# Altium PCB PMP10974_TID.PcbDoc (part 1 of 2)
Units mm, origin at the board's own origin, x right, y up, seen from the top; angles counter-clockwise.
Board outline 80 x 60 mm, 2 copper layers (Top Layer, Bottom Layer), stack 1.575 mm thick; 90 components, 52 nets, 298 pads, 61 vias.
Unrouted connection lines stored in the file: 1.
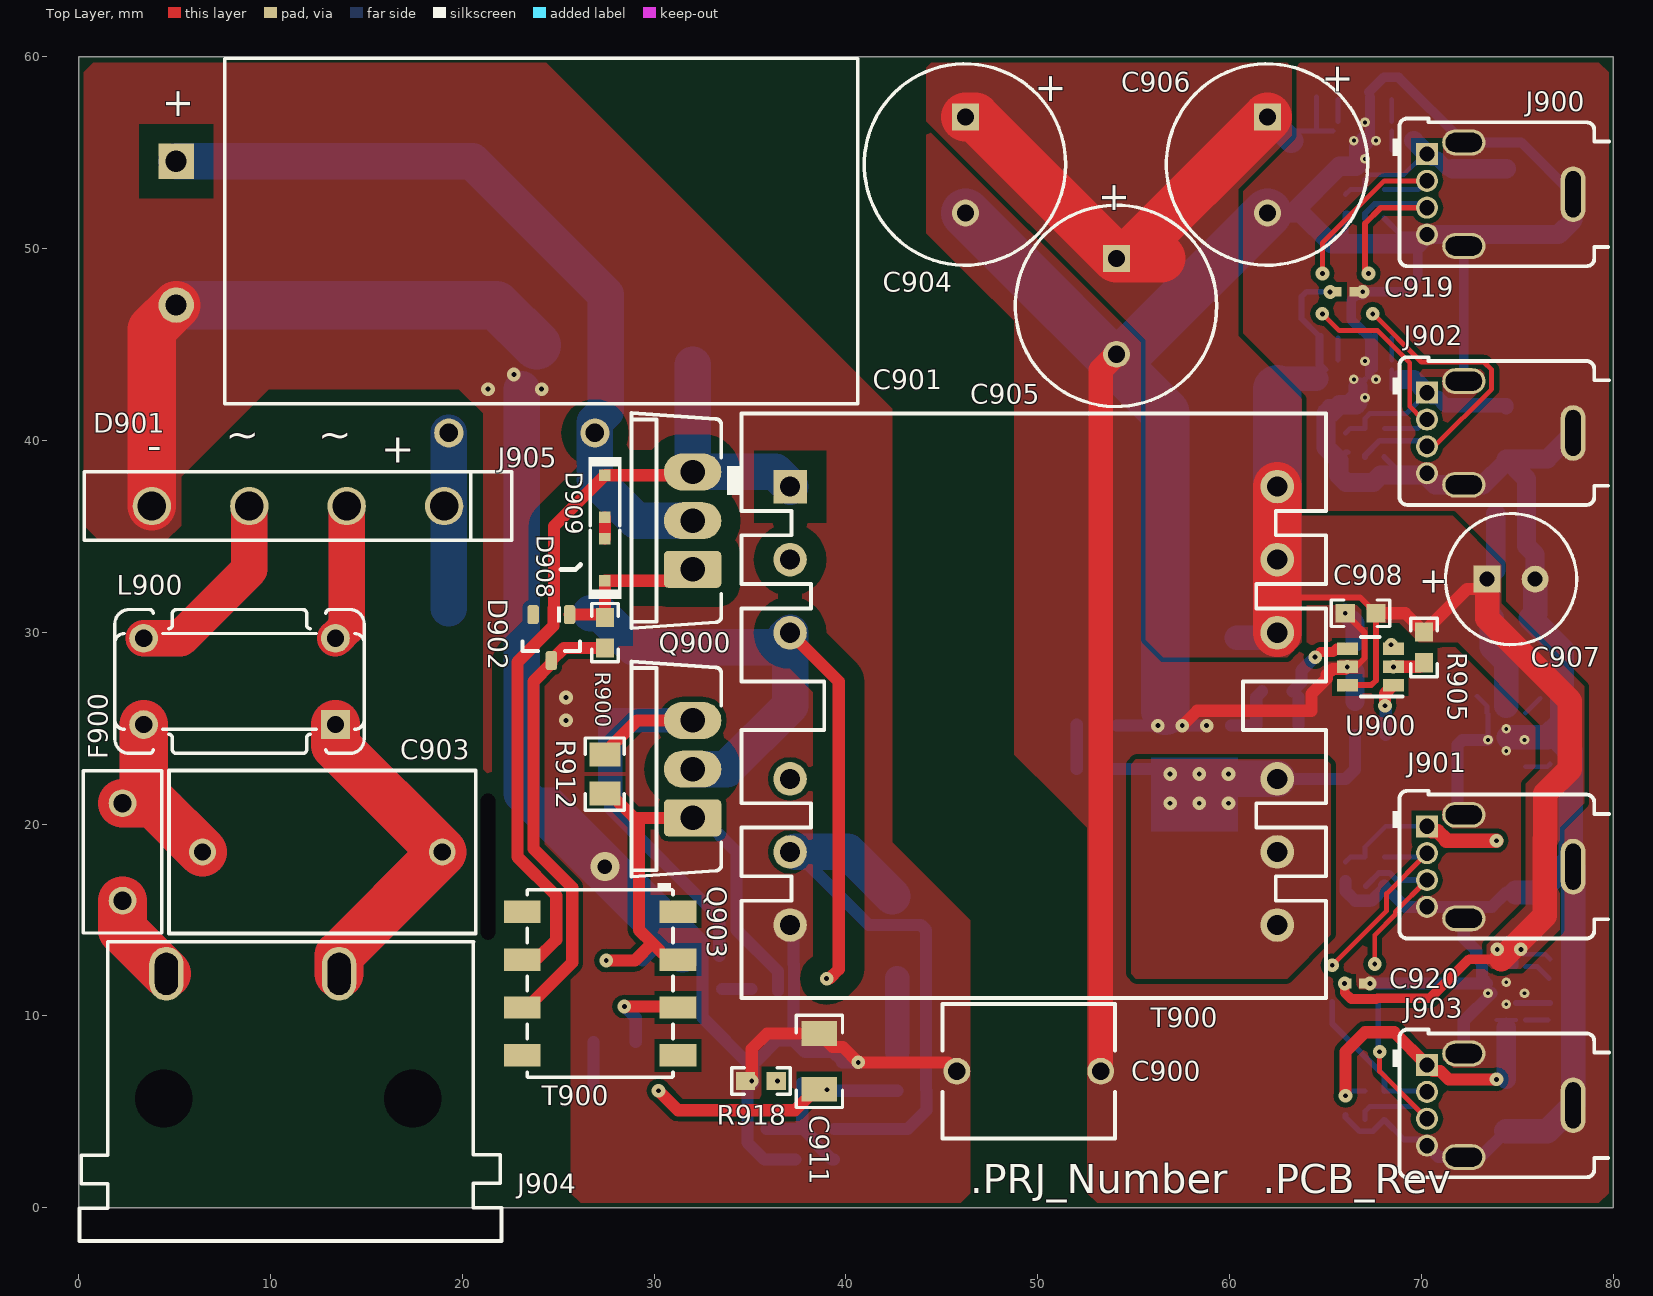
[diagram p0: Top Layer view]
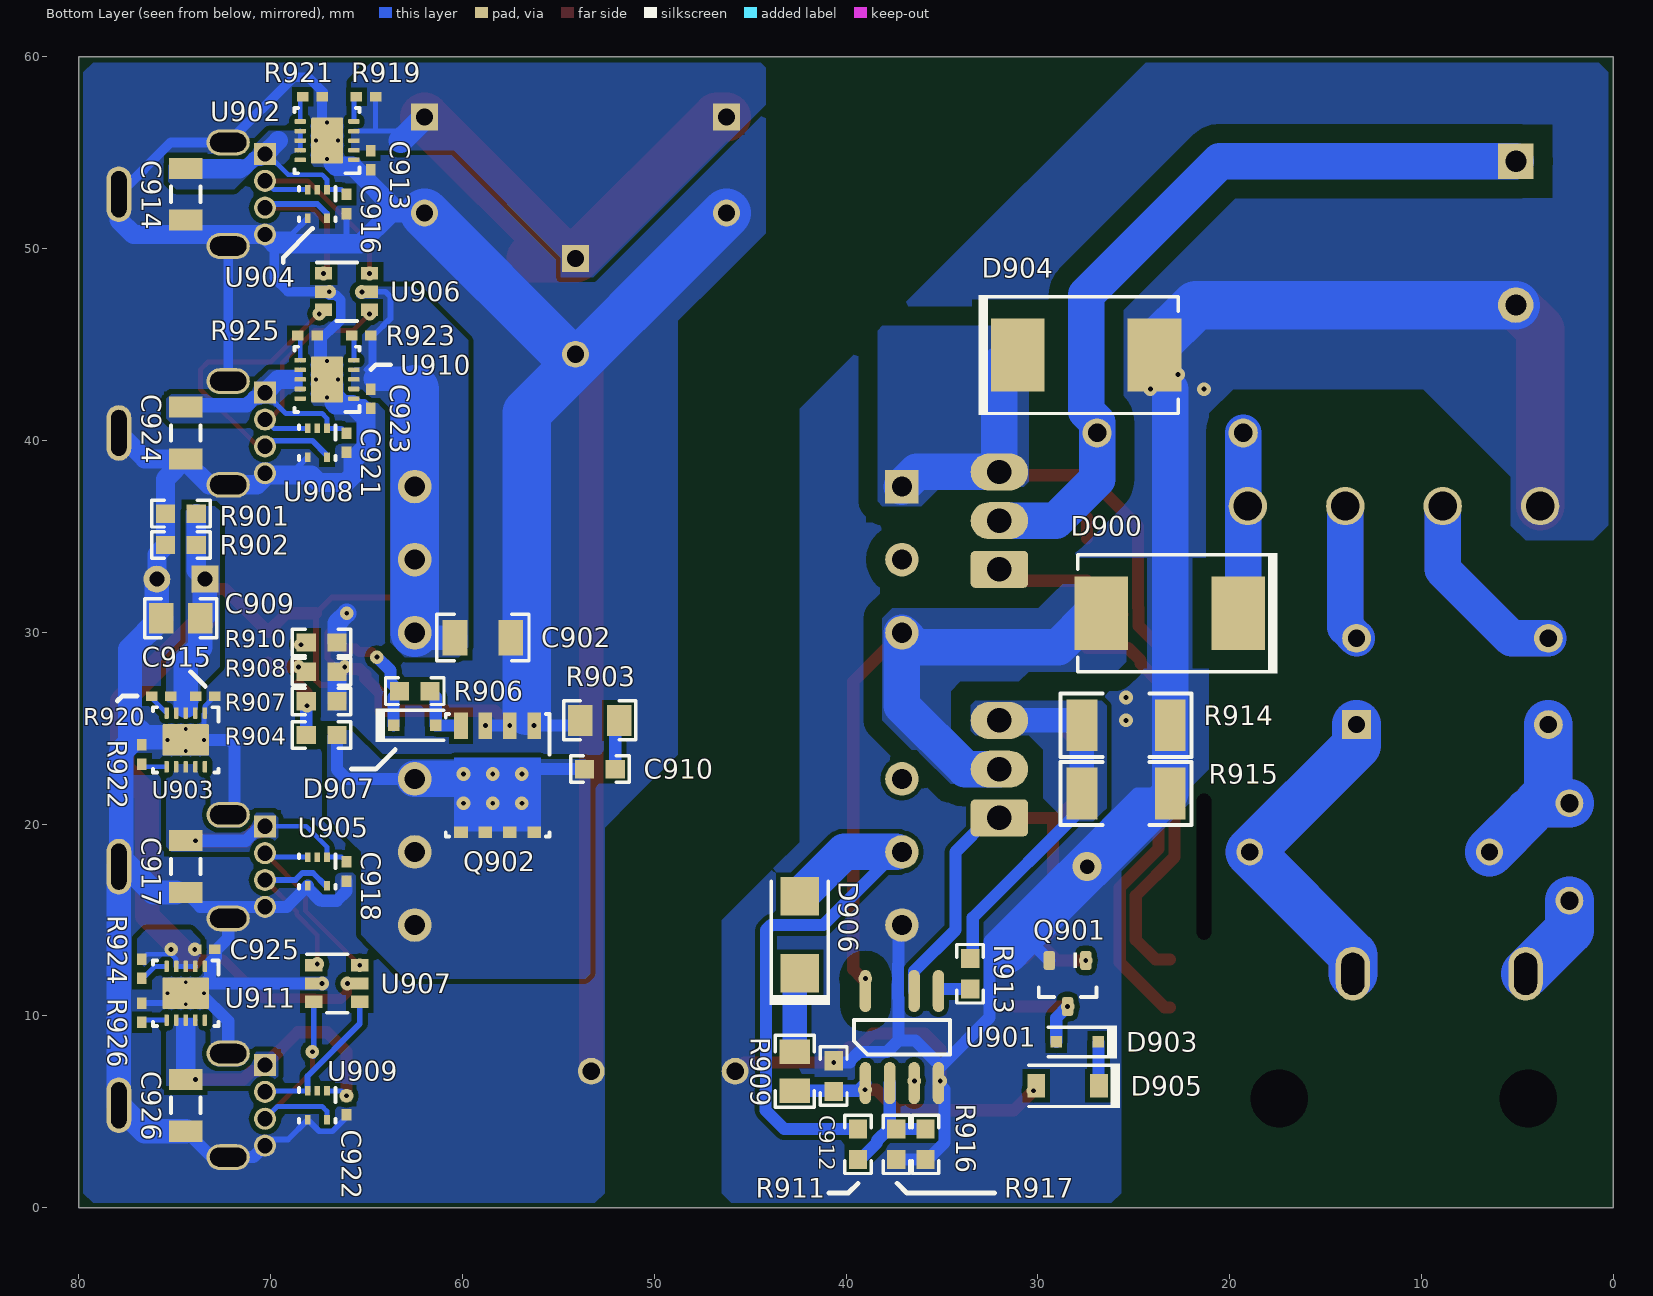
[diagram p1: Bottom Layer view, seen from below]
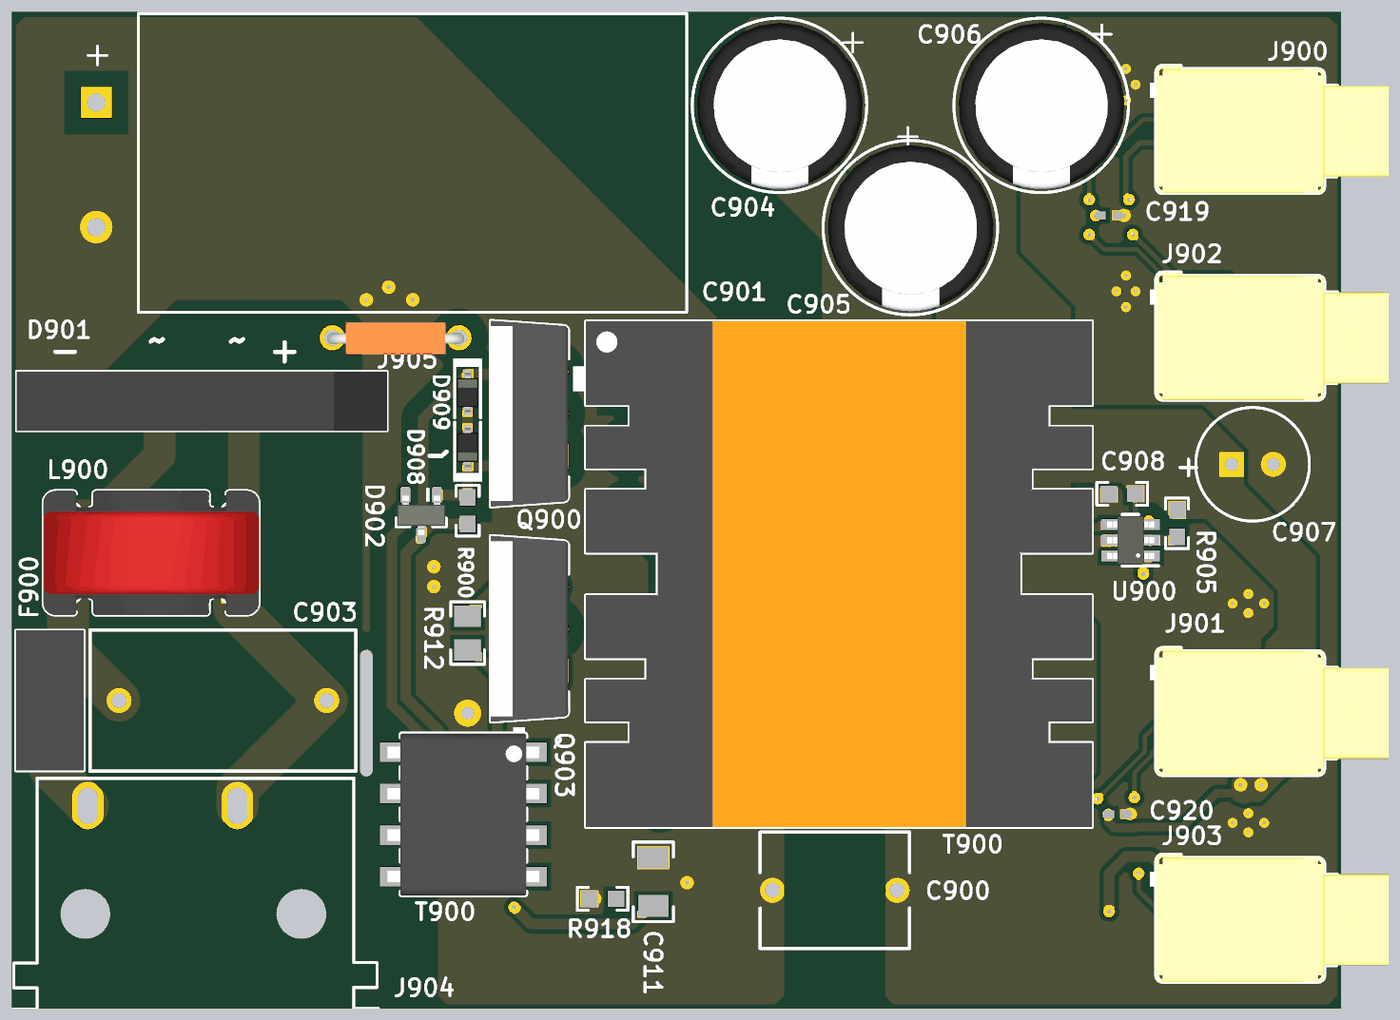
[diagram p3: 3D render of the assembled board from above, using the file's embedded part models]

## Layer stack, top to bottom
Top Solder: solder mask 0.0102, Solder Resist, Dk 3.5
Top Layer: signal copper 0.0356
Dielectric1: core 1.5037, FR-4, Dk 4.8
Bottom Layer: signal copper 0.0356
Bottom Solder: solder mask 0.0102, Solder Resist, Dk 3.5

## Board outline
0,0 80,0 80,60 0,60

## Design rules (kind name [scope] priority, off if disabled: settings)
AcuteAngle [All] p1: minimum=4.50000000000000E+0001 checktracksonly=FALSE
AssemblyTestPointUsage [All] p1: valid=2
Clearance Clearance_1 [InNetClass('HV') vs InNet('GND')] p1: gap=1
Clearance Clearance_Keepouts [((IsTrack Or IsArc) And Not InPoly) And IsFree and IsKeepOut vs ((IsTrack Or IsArc) And Not InPoly) And IsFree and IsKeepOut] p2: gap=0
Clearance Clearance_BoardEdge_MountingHoles [OnCopper and InComponentClass('Mounting Holes') vs IsKeepOut] p3: gap=1.016
Clearance Clearance_BoardEdge_Poly [OnCopper and InPoly vs IsKeepOut] p4: gap=0.635
Clearance Clearance_BoardEdge [OnCopper and Not InComponentClass('Logo') and not InComponentClass('FiducialMark') and not InRegion(1000,500,4000,800) and Not IsKeepout vs IsKeepOut] p5: gap=1.905
Clearance Clearance_Poly [InPolygon] p6: gap=0.254
Clearance [All] p7: gap=0.2
ComponentClearance ComponentClearance_MountingHoles_FiducialMarks [InComponentClass('Mounting Holes') vs InComponentClass('FiducialMark')] p1: gap=0.508 collisioncheckmode=3 verticalgap=0.254 showdistances=FALSE
ComponentClearance ComponentClearance_Shunt [InComponentClass('Header') vs InComponentClass('Shunt')] p2: gap=0 collisioncheckmode=3 verticalgap=0 showdistances=FALSE
ComponentClearance ComponentClearance_Logo [InComponentClass('Logo')] p3: gap=0.127 collisioncheckmode=3 verticalgap=0.254 showdistances=FALSE
ComponentClearance ComponentClearance_ScrewToNut [(HasFootprint('NY PMS 440 0025 PH')) vs (HasFootprint('Keystone_1902C'))] p4: gap=0.508 collisioncheckmode=3 verticalgap=2540 showdistances=FALSE
ComponentClearance ComponentClearance_MountingHoles [InComponentClass('Mounting Holes')] p5: gap=0.508 collisioncheckmode=3 verticalgap=0.254 showdistances=FALSE
ComponentClearance ComponentClearance_SmallPassives [HasFootprint('0201*') or HasFootprint('0402*') or HasFootprint('0508') or HasFootprint('0603*') or HasFootprint('0612') or HasFootprint('0805*') or HasFootprint('0815*') or HasFootprint('0830*') or HasFootprint('1206*') or HasFootprint('1210*') or HasFootprint('1808*') or HasFootprint('1812*') or HasFootprint('1825*') or HasFootprint('2010*') or HasFootprint('2220*') or HasFootprint('2225*') or HasFootprint('2512*') or HasFootprint('2728*') or HasFootprint('3518*') vs HasFootprint('0201*') or HasFootprint('0402*') or HasFootprint('0508') or HasFootprint('0603*') or HasFootprint('0612') or HasFootprint('0805*') or HasFootprint('0815*') or HasFootprint('0830*') or HasFootprint('1206*') or HasFootprint('1210*') or HasFootprint('1808*') or HasFootprint('1812*') or HasFootprint('1825*') or HasFootprint('2010*') or HasFootprint('2220*') or HasFootprint('2225*') or HasFootprint('2512*') or HasFootprint('2728*') or HasFootprint('3518*')] p6: gap=0.508 collisioncheckmode=3 verticalgap=0.508 showdistances=FALSE
ComponentClearance ComponentClearance_THtoSMT [IsThruComponent vs IsSMTComponent] p7: gap=0.254 collisioncheckmode=3 verticalgap=0.254 showdistances=FALSE
ComponentClearance ComponentClearance_THtoTH [IsThruComponent vs IsThruComponent] p8: gap=0.254 collisioncheckmode=3 verticalgap=0.254 showdistances=FALSE
ComponentClearance [All] p9: gap=0.254 collisioncheckmode=3 verticalgap=0.254 showdistances=FALSE
DiffPairsRouting [All] p1: maxlimit=2.54 minlimit=0.254 mostfreqgap=0.254 toplayer_minwidth=0.381 toplayer_maxwidth=0.381 toplayer_prefwidth=0.381 bottomlayer_minwidth=0.381 bottomlayer_maxwidth=0.381 bottomlayer_prefwidth=0.381 maxuncoupledlength=25.4
FabricationTestPointUsage TestPointUsage [All] p1: valid=2 allowmultiple=FALSE
FabricationTestpoint Testpoint [All] p1: side=3 testpointundercomponent=TRUE minsize=1.016 maxsize=2.54 preferedsize=1.524 minholesize=0 maxholesize=1.016 preferedholesize=0.813 testpointgrid=0.025 allowsidetop=TRUE allowsidebottom=TRUE usegrid=TRUE gridtolerance=0
FanoutControl Fanout_LCC [IsLCC] p1: bgadir=Out bgaviamode=Centered fanoutstyle=Auto fanoutdirection=Alternating viagrid=0.025 // Fanout_LCC (Default Rule)
FanoutControl Fanout_BGA [IsBGA] p2: bgadir=Out bgaviamode=Centered fanoutstyle=Auto fanoutdirection=Alternating viagrid=0.025 // Fanout_BGA (Default Rule)
FanoutControl Fanout_Default [All] p4: bgadir=Out bgaviamode=Centered fanoutstyle=Auto fanoutdirection=Alternating viagrid=0.025 // Fanout_Default (Default Rule)
FanoutControl Fanout_Small [(CompPinCount < 5)] p5: bgadir=Out bgaviamode=Centered fanoutstyle=Auto fanoutdirection=OutThenIn viagrid=0.025 // Fanout_Small (Default Rule)
Height [All] p1: minheight=0 maxheight=76.2 prefheight=12.7
HoleSize [All] p1: absolutevalues=TRUE maxlimit=20 minlimit=0.178 maxpercent=80.000 minpercent=20.000
MinimumAnnularRing MinimumAnnularRing_ThermalPadVias [IsVia and InAnyComponent] p1: minimumring=0.15
MinimumAnnularRing [All] p2: minimumring=0.15
MinimumSolderMaskSliver MinimumSolderMaskSliver_Logo [InComponentClass('Logo') vs InComponentClass('Logo')] p1: minsoldermaskwidth=0.018
MinimumSolderMaskSliver [All] p2: minsoldermaskwidth=0.051
PlaneConnect [All] p1: planeconnectstyle=Relief reliefexpansion=0.254 reliefentries=4 reliefconductorwidth=0.254 reliefairgap=0.254
PolygonConnect PolygonConnect_12 [All vs IsNamedPolygon('C910_2') Or  IsNamedPolygon('C917_1') Or  IsNamedPolygon('GND') Or  IsNamedPolygon('Vout') Or  IsNamedPolygon('D904_1') Or  IsNamedPolygon('Vout') Or  IsNamedPolygon('C922_1') Or  IsNamedPolygon('C910_2') Or  IsNamedPolygon('Vout') Or  IsNamedPolygon('GND') Or  IsNamedPolygon('C914') Or  IsNamedPolygon('GND') Or  IsNamedPolygon('Vout') Or  IsNamedPolygon('Vout') Or  IsNamedPolygon('Q903_3') Or  IsNamedPolygon('C921_1') Or  IsNamedPolygon('D900_2') Or  IsNamedPolygon('Vout')] p1: connectstyle=Direct reliefconductorwidth=0.254 reliefentries=4 polygonreliefangle="90 Angle" airgapwidth=0.254
PolygonConnect PolygonConnect_11 [All vs IsNamedPolygon('Vout') Or  IsNamedPolygon('Vout') Or  IsNamedPolygon('Vout') Or  IsNamedPolygon('C917_1') Or  IsNamedPolygon('D904_1') Or  IsNamedPolygon('Vout') Or  IsNamedPolygon('D900_2') Or  IsNamedPolygon('C910_2') Or  IsNamedPolygon('Vout') Or  IsNamedPolygon('C921_1') Or  IsNamedPolygon('Q903_3') Or  IsNamedPolygon('Vout') Or  IsNamedPolygon('C914') Or  IsNamedPolygon('C922_1') Or  IsNamedPolygon('C910_2')] p2: connectstyle=Direct reliefconductorwidth=0.254 reliefentries=4 polygonreliefangle="90 Angle" airgapwidth=0.254
PolygonConnect PolygonConnect_10 [All vs IsNamedPolygon('Vout')] p3: connectstyle=Direct reliefconductorwidth=0.254 reliefentries=4 polygonreliefangle="90 Angle" airgapwidth=0.254
PolygonConnect PolygonConnect_9 [All vs IsNamedPolygon('C921_1') Or  IsNamedPolygon('D904_1') Or  IsNamedPolygon('Vout') Or  IsNamedPolygon('C914') Or  IsNamedPolygon('C917_1') Or  IsNamedPolygon('C910_2') Or  IsNamedPolygon('Vout') Or  IsNamedPolygon('Q903_3') Or  IsNamedPolygon('Vout') Or  IsNamedPolygon('Vout') Or  IsNamedPolygon('D900_2') Or  IsNamedPolygon('C910_2')] p4: connectstyle=Direct reliefconductorwidth=0.254 reliefentries=4 polygonreliefangle="90 Angle" airgapwidth=0.254
PolygonConnect PolygonConnect_8 [All vs IsNamedPolygon('C910_2') Or  IsNamedPolygon('D904_1') Or  IsNamedPolygon('Vout') Or  IsNamedPolygon('C910_2') Or  IsNamedPolygon('Q903_3') Or  IsNamedPolygon('C914') Or  IsNamedPolygon('D900_2') Or  IsNamedPolygon('Vout')] p5: connectstyle=Direct reliefconductorwidth=0.254 reliefentries=4 polygonreliefangle="90 Angle" airgapwidth=0.254
PolygonConnect PolygonConnect_7 [All vs IsNamedPolygon('C910_2') Or  IsNamedPolygon('Q903_3') Or  IsNamedPolygon('Vout') Or  IsNamedPolygon('Vout') Or  IsNamedPolygon('D904_1') Or  IsNamedPolygon('D900_2') Or  IsNamedPolygon('C910_2')] p6: connectstyle=Direct reliefconductorwidth=0.254 reliefentries=4 polygonreliefangle="90 Angle" airgapwidth=0.254
PolygonConnect PolygonConnect_6 [All vs IsNamedPolygon('GND2') Or  IsNamedPolygon('SGND') Or  IsNamedPolygon('GND1') Or  IsNamedPolygon('C901_1') Or  IsNamedPolygon('SGND') Or  IsNamedPolygon('GND2') Or  IsNamedPolygon('GND1')] p7: connectstyle=Direct reliefconductorwidth=0.254 reliefentries=4 polygonreliefangle="90 Angle" airgapwidth=0.254
PolygonConnect PolygonConnect_5 [All vs IsNamedPolygon('GND1') Or  IsNamedPolygon('GND1')] p8: connectstyle=Direct reliefconductorwidth=0.254 reliefentries=4 polygonreliefangle="90 Angle" airgapwidth=0.254
PolygonConnect PolygonConnect_4 [All vs IsNamedPolygon('C21_1') Or  IsNamedPolygon('C5_1') Or  IsNamedPolygon('C12_2') Or  IsNamedPolygon('C2_2') Or  IsNamedPolygon('C13_1') Or  IsNamedPolygon('C28_1') Or  IsNamedPolygon('C6_1') Or  IsNamedPolygon('GND') Or  IsNamedPolygon('GND2') Or  IsNamedPolygon('C14_1') Or  IsNamedPolygon('C13_1') Or  IsNamedPolygon('Q1_3') Or  IsNamedPolygon('C14_1') Or  IsNamedPolygon('C5_1') Or  IsNamedPolygon('GND2') Or  IsNamedPolygon('C28_1') Or  IsNamedPolygon('D5_2') Or  IsNamedPolygon('D6_2') Or  IsNamedPolygon('D2_1') Or  IsNamedPolygon('C12_2') Or  IsNamedPolygon('D2_1') Or  IsNamedPolygon('C4_1') Or  IsNamedPolygon('C4_1') Or  IsNamedPolygon('C2_2') Or  IsNamedPolygon('GND') Or  IsNamedPolygon('C33_1') Or  IsNamedPolygon('C9_1')] p9: connectstyle=Direct reliefconductorwidth=0.254 reliefentries=4 polygonreliefangle="90 Angle" airgapwidth=0.254
PolygonConnect PolygonConnect_3 [All vs IsNamedPolygon('C28_1') Or  IsNamedPolygon('C12_2') Or  IsNamedPolygon('C28_1') Or  IsNamedPolygon('C9_1') Or  IsNamedPolygon('D5_2') Or  IsNamedPolygon('C12_2') Or  IsNamedPolygon('C2_2') Or  IsNamedPolygon('C14_1') Or  IsNamedPolygon('C4_1') Or  IsNamedPolygon('C14_1') Or  IsNamedPolygon('D6_2') Or  IsNamedPolygon('GND2') Or  IsNamedPolygon('Q1_3') Or  IsNamedPolygon('C5_1') Or  IsNamedPolygon('D2_1') Or  IsNamedPolygon('C4_1') Or  IsNamedPolygon('C13_1') Or  IsNamedPolygon('C5_1') Or  IsNamedPolygon('C13_1') Or  IsNamedPolygon('C33_1') Or  IsNamedPolygon('D2_1') Or  IsNamedPolygon('GND') Or  IsNamedPolygon('GND') Or  IsNamedPolygon('GND2') Or  IsNamedPolygon('C2_2') Or  IsNamedPolygon('C6_1') Or  IsNamedPolygon('C21_1')] p10: connectstyle=Direct reliefconductorwidth=0.254 reliefentries=4 polygonreliefangle="90 Angle" airgapwidth=0.254
PolygonConnect PolygonConnect_2 [All vs IsNamedPolygon('C21_1') Or  IsNamedPolygon('C4_1') Or  IsNamedPolygon('D5_2') Or  IsNamedPolygon('C5_1') Or  IsNamedPolygon('C14_1') Or  IsNamedPolygon('C13_1') Or  IsNamedPolygon('C4_1') Or  IsNamedPolygon('C33_1') Or  IsNamedPolygon('C12_2') Or  IsNamedPolygon('D2_1') Or  IsNamedPolygon('C2_2') Or  IsNamedPolygon('C28_1') Or  IsNamedPolygon('C12_2') Or  IsNamedPolygon('D2_1') Or  IsNamedPolygon('C5_1') Or  IsNamedPolygon('Q1_3') Or  IsNamedPolygon('GND') Or  IsNamedPolygon('D6_2') Or  IsNamedPolygon('C6_1') Or  IsNamedPolygon('C2_2') Or  IsNamedPolygon('C14_1') Or  IsNamedPolygon('C28_1') Or  IsNamedPolygon('C13_1') Or  IsNamedPolygon('C9_1') Or  IsNamedPolygon('GND')] p11: connectstyle=Direct reliefconductorwidth=0.254 reliefentries=4 polygonreliefangle="90 Angle" airgapwidth=0.254
PolygonConnect PolygonConnect_1 [All vs IsNamedPolygon('C28_1') Or  IsNamedPolygon('D5_2') Or  IsNamedPolygon('C5_1') Or  IsNamedPolygon('C5_1') Or  IsNamedPolygon('D2_1') Or  IsNamedPolygon('C21_1') Or  IsNamedPolygon('C9_1') Or  IsNamedPolygon('C4_1') Or  IsNamedPolygon('C14_1') Or  IsNamedPolygon('C28_1') Or  IsNamedPolygon('C6_1') Or  IsNamedPolygon('C12_2') Or  IsNamedPolygon('C33_1') Or  IsNamedPolygon('C4_1') Or  IsNamedPolygon('C13_1') Or  IsNamedPolygon('C12_2') Or  IsNamedPolygon('D6_2') Or  IsNamedPolygon('C2_2') Or  IsNamedPolygon('C14_1') Or  IsNamedPolygon('D2_1') Or  IsNamedPolygon('C2_2') Or  IsNamedPolygon('C13_1')] p12: connectstyle=Direct reliefconductorwidth=0.254 reliefentries=4 polygonreliefangle="90 Angle" airgapwidth=0.254
PolygonConnect [All] p13: connectstyle=Relief reliefconductorwidth=0.254 reliefentries=4 polygonreliefangle="90 Angle" airgapwidth=0.254
RoutingVias ThermalPadVias [IsVia and InAnyComponent] p1: holewidth=0.2 width=0.5 viastyle="Through Hole" minholewidth=0.2 minwidth=0.5 maxholewidth=0.33 maxwidth=0.6
RoutingVias [All] p2: holewidth=0.406 width=0.864 viastyle="Through Hole" minholewidth=0.2 minwidth=0.66 maxholewidth=1.016 maxwidth=1.651
SilkToBoardRegionClearance [Not ((IsComment or IsDesignator) And (Hide <> 'False')) and not InRegion(1000,500,4000,800)] p1:
SilkToSilkClearance SilkToSilkClearance_Pb-FreeLogo [(HasFootprint('Pb-Free_Overlay_Medium') OR HasFootprint('Pb-Free_Overlay_Small')) vs (HasFootprint('Pb-Free_Overlay_Medium') OR HasFootprint('Pb-Free_Overlay_Small'))] p1: silktosilkclearance=0
SilkToSilkClearance [All] p2: silktosilkclearance=0.025
SilkToSolderMaskClearance "Silk to Solder Mask Opening" [All] p1: minsilkscreentomaskgap=0.025 clearancetoexposedcopper=FALSE
SolderMaskExpansion [All] p1: expansion=0.05
UnpouredPolygon [All] p1: allowunpoured=FALSE
Width [All] p1: maxlimit=2.54 minlimit=0.152 preferedwidth=0.254 checkconnectedcopper=TRUE
13 further rules are at their usual default settings.

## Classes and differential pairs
component class PMP10974_BlankSheet: !PCB900 C900 C901 C902 C903 C904 C905 C906 C907 C908 C909 C910 C911 C912 D900 D901 D902 D903 D904 D905 D906 D907 D908 D909 F900 J904 J905 L900 Q900 Q901 Q902 Q903 R900 R901 R902 R903 R904 R905 R906 R907 R908 R909 R910 R911 R912 R913 R914 R915 R916 R917 R918 T900 U900 U901
component class PMP10974_TID_Hardware: C913 C914 C915 C916 C917 C918 C919 C920 C921 C922 C923 C924 C925 C926 J900 J901 J902 J903 R919 R920 R921 R922 R923 R924 R925 R926 U902 U903 U904 U905 U906 U907 U908 U909 U910 U911
net class HV: NetC901_1 NetC903_1 NetC903_2 NetD900_1 NetD900_2 NetD901_2 NetD901_3 NetD902_1 NetD904_1

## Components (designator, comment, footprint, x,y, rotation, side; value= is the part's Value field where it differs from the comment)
C900 "DE6E3KJ222MN3A" E_900x700x900 49.53,7.112 r180 top
C901 "UPT2G101MHD6" CAPPR7.5-18X25 5.08,50.8 r270 top
C902 "1206YD226MAT2A" 1206 58.928,29.718 r180 bottom
C903 "890324024003" ECQUG_1500x800x1500 12.7,18.542 r0 top
C904 "PLE0J681MDO1" CAPPRD500W60D1000H1250 46.228,54.356 r270 top
C905 "PLE0J681MDO1" CAPPRD500W60D1000H1250 54.102,46.99 r270 top
C906 "PLE0J681MDO1" CAPPRD500W60D1000H1250 61.976,54.356 r270 top
C907 "6.3YXJ470M6.3X11" SEPC_C55 74.676,32.766 r0 top
C908 "C0603C105K4PACTU" 0603 66.828,30.988 r180 top
C909 "08053C104KAT2A" 0805_HV 74.676,30.734 r0 bottom
C910 "C1608C0G2A101J" 0603 52.832,22.86 r0 bottom
C911 "GRM316R61E225KA12D" 1206 38.608,7.62 r90 top
C912 "06035C104KAT2A" 0603 40.64,6.858 r90 bottom
C913 "GRM155R61A105KE15D" 0402L 64.77,54.61 r270 bottom
C914 "GRM31CR61A476KE15L" 1206L 74.422,52.832 r270 bottom
C915 "GRM155R61A105KE15D" 0402L 73.406,26.67 r180 bottom
C916 "C1005X5R0J104K" 0402L 66.04,52.324 r270 bottom
C917 "GRM31CR61A476KE15L" 1206L 74.422,17.78 r270 bottom
C918 "C1005X5R0J104K" 0402L 66.04,17.526 r270 bottom
C919 "GRM155R61A105KE15D" 0402L 66.04,47.752 r0 top
C920 "GRM155R61A105KE15D" 0402L 66.548,11.684 r0 top
C921 "C1005X5R0J104K" 0402L 66.04,39.878 r270 bottom
C922 "C1005X5R0J104K" 0402L 66.04,5.334 r270 bottom
C923 "GRM155R61A105KE15D" 0402L 64.77,42.164 r270 bottom
C924 "GRM31CR61A476KE15L" 1206L 74.422,40.386 r270 bottom
C925 "GRM155R61A105KE15D" 0402L 73.406,13.462 r180 bottom
C926 "GRM31CR61A476KE15L" 1206L 74.422,5.334 r270 bottom
D900 "MURS360T3G" SMC 23.114,30.988 r0 bottom
D901 "GBU4K-E3/45" GBU 11.43,36.576 r180 top
D902 "BAT54-7-F" SOT-23 24.638,29.718 r270 top
D903 "BAS316,115" sod-323 27.94,8.636 r0 bottom
D904 "MURS360T3G" SMC 27.483,44.45 r180 bottom
D905 "MMSZ5231B-7-F" SOD-123 28.448,6.35 r0 bottom
D906 "ES1D-13-F" SMA 42.418,14.224 r90 bottom
D907 "BAT54HT1G" sod-323 62.484,25.146 r180 bottom
D908 "BAT54HT1G" sod-323 27.432,33.782 r90 top
D909 "MMSZ5246BS-7-F" sod-323 27.432,37.084 r270 top
F900 "RST 500" Fuse_RST 2.286,18.542 r270 top
J900 "0894858000" Molex_0894858000 80,52.832 r0 top
J901 "0894858000" Molex_0894858000 80,17.78 r0 top
J902 "0894858000" Molex_0894858000 80,40.386 r0 top
J903 "0894858000" Molex_0894858000 80,5.334 r0 top
J904 "770W-X2/10" CONN_AC_770W-SERIES 10.922,8.89 r180 top
J905 "923345-03-C" 923345-03-C 23.1,40.386 r0 top
L900 "744821240" WE-CMB_XS 8.382,27.432 r180 top
Q900 "IPP50R380CE" TO-220AB 32.004,35.814 r90 top
Q901 "2N7002-7-F" SOT-23 28.448,11.684 r270 bottom
Q902 "CSD18502Q5B" TRANS_NexFET_Q5B 58.166,22.352 r270 bottom
Q903 "IPP50R380CE" TO-220AB 32.004,22.86 r90 top
R900 "CRCW06033R00JNEA" 0603 27.432,29.972 r90 top
R901 "CRCW0603100KJNEA" 0603 74.676,36.176 r180 bottom
R902 "CRCW06031K00JNEA" 0603 74.676,34.544 r180 bottom
R903 "CRCW08050000Z0EA" 0805_HV 52.832,25.4 r0 bottom
R904 "CRCW0603324KFKEA" 0603 67.336,24.638 r180 bottom
R905 "CRCW0603182KFKEA" 0603 70.13,29.21 r90 top
R906 "CRCW06030000Z0EA" 0603 62.484,26.924 r0 bottom
R907 "CRCW060310K0FKEA" 0603 67.336,26.394 r0 bottom
R908 "CRCW060330K1FKEA" 0603 67.336,27.94 r0 bottom
R909 "CRCW080510R0FKEA" 0805_HV 42.672,7.112 r90 bottom
R910 "CRCW060325K5FKEA" 0603 67.336,29.464 r180 bottom
R911 "CRCW0603133KFKEA" 0603 39.37,3.302 r90 bottom
R912 "CRCW0805100KJNEA" 0805_HV 27.432,22.606 r270 top
R913 "CRCW0603976RFKEA" 0603 33.528,12.192 r90 bottom
R914 "MCR50JZHFLR330" 2010 25.4,25.146 r0 bottom
R915 "CSRN2010FKR400" 2010 25.4,21.59 r0 bottom
R916 "CRCW060356K2FKEA" 0603 35.851,3.302 r90 bottom
R917 "CRCW060356K2FKEA" 0603 37.375,3.302 r90 bottom
R918 "CRCW060336K5FKEA" 0603 35.56,6.604 r0 top
R919 "CRCW040210K0FKED" 0402L 65.024,57.912 r180 bottom
R920 "CRCW040210K0FKED" 0402L 75.692,26.67 r180 bottom
R921 "CRCW040244K2FKED" 0402L 67.818,57.912 r0 bottom
R922 "CRCW040244K2FKED" 0402L 76.708,23.622 r270 bottom
R923 "CRCW040210K0FKED" 0402L 65.278,45.466 r180 bottom
R924 "CRCW040210K0FKED" 0402L 76.708,12.446 r90 bottom
R925 "CRCW040244K2FKED" 0402L 68.072,45.466 r0 bottom
R926 "CRCW040244K2FKED" 0402L 76.708,10.16 r270 bottom
T900 "760301302" Wurth_760301302 27.178,11.684 r270 top
T900 "RLTI-1132" Renco_RLTI-1132 49.784,26.162 r0 top
U900 "UCC24630DBV" DBV0006A_N 67.336,28.194 r180 top
U901 "UCC28730D" D0007A_N 37.084,8.89 r90 bottom
U902 "TPS2559DRC" DRC0010A 67.056,55.626 r0 bottom
U903 "TPS2559DRC" DRC0010A 74.422,24.384 r270 bottom
U904 "TPD2E001DRLR" DRL0005A 67.564,52.324 r270 bottom
U905 "TPD2E001DRLR" DRL0005A 67.564,17.526 r270 bottom
U906 "TPS2513DBV" DBV0006A_L 66.04,47.752 r180 bottom
U907 "TPS2513DBV" DBV0006A_L 66.548,11.684 r180 bottom
U908 "TPD2E001DRLR" DRL0005A 67.564,39.878 r270 bottom
U909 "TPD2E001DRLR" DRL0005A 67.564,5.334 r270 bottom
U910 "TPS2559DRC" DRC0010A 67.056,43.18 r0 bottom
U911 "TPS2559DRC" DRC0010A 74.422,11.176 r270 bottom

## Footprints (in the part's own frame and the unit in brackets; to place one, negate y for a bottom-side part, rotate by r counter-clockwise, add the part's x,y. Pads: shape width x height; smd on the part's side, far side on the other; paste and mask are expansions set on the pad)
0402L [mm] "0402 from SM-752 data"
  rect 0.6x0.5 smd: 1(-0.5,0) 2(0.5,0)
  body extent -0.55,-0.3 0.55,0.3, height 0.6
0603 [mm] "0603 from SM-752 data"
  rect 1x0.95 smd: 1(-0.8,0) 2(0.8,0)
  silkscreen extent -1.52,-0.69 1.52,0.69, body extent -0.87,-0.47 0.87,0.47, height 0.85
0805_HV [mil] "0805 with 30mil clearance between pads"
  rect 50x63 smd: 1(-40,0) 2(40,0)
  silkscreen extent -74,-40 74,40, body extent -43,-29 43,29, height 43
1206 [mm] "1206 from SM-752 data"
  rect 1.3x1.85 smd: 1(-1.45,0) 2(1.45,0)
  silkscreen extent -2.4,-1.21 2.4,1.21, body extent -1.7,-0.9 1.7,0.9, height 1.35
1206L [mm] "1206 from SM-752 data"
  rect 1.1x1.75 smd: 1(-1.35,0) 2(1.35,0)
  silkscreen extent -0.4,-0.77 0.4,0.77, body extent -1.7,-0.9 1.7,0.9, height 1.35
2010 [mm] "Chip Capacitor, Body 5.08x2.54mm, IPC Medium Density"
  rect 1.6x2.7 smd: 1(-2.3,0) 2(2.3,0)
  silkscreen extent -3.42,-1.65 3.42,1.65, body extent -2.73,-1.45 2.73,1.45, height 1.66
923345-03-C [mil] "Wire Jumper"
  round 60 hole 38: 1(-150,0) 2(150,0)
  body extent -163,-40 163,37, height 100
CAPPR7.5-18X25 [mm] "Capacitor, Electrolytic, Radial; Body 18 x 25 mm (Dia.xH typ); Pin Spacing 7.5 mm (typ)"
  rect 1.85x1.85 hole 1.1: 1(-3.75,0)
  round 1.85 hole 1.1: 2(3.75,0)
  body extent -9.01,-9.01 9.01,9.01, height 27
CAPPRD500W60D1000H1250 [mm] "Capacitor, Electrolytic, Radial; Body 10 x 12.5 mm (Dia.xH typ); Pin Spacing 5 mm (typ)"
  rect 1.4x1.4 hole 0.889: 1(-2.5,0)
  round 1.4 hole 0.889: 2(2.5,0)
  silkscreen extent -5.27,-5.27 5.22,5.22, body extent -5,-4.99 5,4.99, height 14.12
CONN_AC_770W-SERIES [mm] "Qualtek Electronics"
  oval 1.8x2.8 hole 1.2 slot 2.2 at 90 deg: 1(6.35,-3.3) 2(-2.65,-3.3)
  round 2 hole 3 unplated: MH1(6.5,3.2) MH2(-6.5,3.2)
  silkscreen extent -11.12,-4.97 10.87,10.63, body extent -11.05,-4.8 10.8,10.6, height 22
D0007A_N [mm] "SOIC, 7-Leads, Body 4.9x3.9mm, Pitch 1.27mm, IPC Medium Density"
  oval 2.2x0.6 smd: 1(-2.4,1.905) 2(-2.4,0.635) 3(-2.4,-0.635) 4(-2.4,-1.905) 5(2.4,-1.905) 6(2.4,-0.635) 8(2.4,1.905)
  silkscreen extent -0.9,-2.5 0.9,2.5, body extent -3,-2.5 3,2.5, height 1.54
DBV0006A_L [mm] "SOT23, 6-Leads, Body 2.9x1.6mm, Pitch 0.95mm, Lead Span 2.8mm, IPC High Density"
  rect 0.9x0.65 smd: 1(-1.2,0.95) 2(-1.2,0) 3(-1.2,-0.95) 4(1.2,-0.95) 5(1.2,0) 6(1.2,0.95)
  silkscreen extent -1.55,-1.53 0.55,1.53, body extent -1.42,-1.46 1.42,1.46, height 1.11
DBV0006A_N [mm] "SOT23, 6-Leads, Body 2.9x1.6mm, Pitch 0.95mm, Lead Span 2.8mm, IPC Medium Density"
  rect 1.1x0.65 smd: 1(-1.2,0.95) 2(-1.2,0) 3(-1.2,-0.95) 4(1.2,-0.95) 5(1.2,0) 6(1.2,0.95)
  silkscreen extent -1.68,-1.55 0.5,1.55, body extent -1.42,-1.46 1.42,1.46, height 1.11
DRC0010A [mm] "SON, 10-Leads, Body 3x3mm, Pitch 0.5mm, Thermal Pad 2.4x1.65mm, TI Recommended"
  rrect42% 0.6x0.24 smd: 1(-1.4,1) 2(-1.4,0.5) 3(-1.4,0) 4(-1.4,-0.5) 5(-1.4,-1) 6(1.4,-1) 7(1.4,-0.5) 8(1.4,0) 9(1.4,0.5) 10(1.4,1)
  rrect6% 1.65x2.4 smd paste-0.825: 11(0,0)
  silkscreen extent -1.7,-1.7 1.7,1.7, body extent -1.55,-1.55 1.55,1.55, height 1.01
DRL0005A [mm] "SOTFL, 5-Flat Leads, Body 1.2x1.6x0.6mm, Pitch 0.5mm, TI recommended"
  rect 0.5x0.3 smd: 1(-0.75,0.5) 2(-0.75,0) 3(-0.75,-0.5) 4(0.75,-0.5) 5(0.75,0.5)
  silkscreen extent -0.9,-0.95 0.9,0.95, body extent -0.85,-0.85 0.85,0.85, height 0.62
E_900x700x900 [mm] "TH, 2- Leads, Body 9x7mm, Pin Spacing 7.5mm"
  round 1.4 hole 0.9: 1(-3.75,0) 2(3.75,0)
  silkscreen extent -4.5,-3.5 4.5,3.5, body extent -4.49,-3.5 4.49,3.5, height 11.96
ECQUG_1500x800x1500 [mm] "TH, 2-Leads, Body 15x8mm, Pin Spacing 12.5mm"
  round 1.4 hole 0.9: 1(-6.25,0) 2(6.25,0)
  silkscreen extent -8,-4.25 8,4.25, body extent -8,-4.25 8,4.25, height 15.5
Fuse_RST [mm] "Bel Fuse RST series May2012D"
  round 1.45 hole 0.95: 1(-2.54,0) 2(2.54,0)
  silkscreen extent -4.23,-2.05 4.23,2.05, body extent -4.22,-2.05 4.23,2.05, height 7.9
GBU [mm] "Comchip / Diodes Inc diode bridge"
  round 2 hole 1.5: 1(-7.62,0) 2(-2.54,0) 3(2.54,0) 4(7.62,0)
  silkscreen extent -11.15,-1.78 11.15,1.78, body extent -11.15,-1.76 11.15,1.8, height 21.55
Molex_0894858000 [mm] "Connector, 7-Leads, Shielded USB Type A, R/A, TH"
  rect 1.15x1.15 hole 0.8: 1(-9.71,2.1)
  round 1.15 hole 0.8: 2(-9.71,0.7) 3(-9.71,-0.7) 4(-9.71,-2.1)
  oval 2.25x1.35 hole 1 slot 1.9 at 0 deg: 5(-7.79,-2.7) 6(-7.79,2.7)
  oval 1.3x2.9 hole 0.8 slot 2.4 at 90 deg: 7(-2.09,0)
  silkscreen extent -11.5,-3.75 -0.23,3.95, body extent -11.14,-3.75 2.86,3.95, height 14.45
Renco_RLTI-1132 [mm] "TH, 12-Leads, Body 1200x1200mil, Pitch 150mil"
  rect 1.75x1.75 hole 1.05: 1(-12.7,11.43)
  round 1.75 hole 1.05: 2(-12.7,7.62) 3(-12.7,3.81) 4(-12.7,-3.81) 5(-12.7,-7.62) 6(-12.7,-11.43) 7(12.7,-11.43) 8(12.7,-7.62) 9(12.7,-3.81) 10(12.7,3.81) 11(12.7,7.62) 12(12.7,11.43)
  silkscreen extent -16,-15.24 15.24,15.24, body extent -15.24,-15.24 15.24,15.24, height 22
SEPC_C55 [mm] "PANASONIC"
  rect 1.4x1.4 hole 0.787: 1(-1.25,0)
  round 1.4 hole 0.787: 2(1.25,0)
  silkscreen extent -3.42,-3.42 3.42,3.42, body extent -3.41,-3.41 3.41,3.41, height 5.52
SMA [mm] "Molded Diode, 2-Leads, Body 4.3x2.6mm, IPC Medium Density, based on OnSemi component dimensions and land pattern"
  rect 2x2 smd: 1(-2,0) 2(2,0)
  silkscreen extent -3.66,-1.57 2.79,1.57, body extent -2.6,-1.3 2.6,1.3, height 2.42
SMC [mil] "Molded Diode, 2-Leads, Body 6.9x5.8mm, IPC Medium Density, based on OnSemi component dimensions and land patterns"
  rect 110x150 smd: 1(-140.49,0) 2(140.49,0)
  silkscreen extent -221,-124 189,124, body extent -156,-116 156,116, height 91
SOD-123 [mm] "On Semi recommended land pattern"
  rect 0.915x1.22 smd: 1(-1.637,0) 2(1.637,0)
  silkscreen extent -2.74,-1.17 2.03,1.17, body extent -1.93,-0.9 1.93,0.9, height 1.35
sod-323 [mm] "NXP recommended land pattern"
  rect 0.6x0.6 smd paste-0.05: 1(-1.1,0) 2(1.1,0)
  silkscreen extent -2.06,-0.86 1.53,0.86, body extent -1.3,-0.67 1.3,0.68, height 1.1
SOT-23 [mm] "SOT23, 3-Leads, Body 2.9x1.3mm, Pitch 0.95mm, Lead Span 2.5mm, IPC Medium Density"
  rrect50% 1x0.6 smd: 1(-1.2,0.95) 2(-1.2,-0.95) 3(1.2,0)
  silkscreen extent -1.63,-1.5 0.7,1.5, body extent -1.16,-1.45 1.21,1.45, height 1
TO-220AB [mm] "Copied from Altium's version of TO3B"
  rrect25% 1.93x3 hole 1.27: 1(-2.54,0)
  oval 1.93x3 hole 1.27: 2(0,0) 3(2.54,0)
  silkscreen extent -5.61,-1.49 5.61,3.2, body extent -5.61,-1.49 5.61,3.2, height 19.42
TRANS_NexFET_Q5B [mm] "TI recommended land pattern (nominal) November 2012"
  rect 1.372x0.71 smd paste-0.4: 1(-2.776,1.905) 2(-2.776,0.635) 3(-2.776,-0.635) 4(-2.776,-1.905)
  rect 0.59x0.71 smd paste-0.3: 5(2.776,-1.905) 6(2.776,-0.635) 7(2.776,0.635) 8(2.776,1.905)
  Top Layer region: -1.106,2.26 2.744,2.26 2.744,-2.26 -1.106,-2.26
  silkscreen extent -3.38,-2.7 3,2.7, body extent -3.23,-2.55 2.87,2.55, height 1.06
WE-CMB_XS [mm] "WE-CMB Series Size XS"
  rect 1.5x1.5 hole 0.9: 1(-5,2.25)
  round 1.5 hole 0.9: 2(-5,-2.25) 3(5,-2.25) 4(5,2.25)
  silkscreen extent -6.5,-3.75 6.5,3.75, body extent -6.5,-3.75 6.5,3.75, height 16.24
Wurth_760301302 [mm] "SMD, 8-Leads, Body 10.5x10.5mm, Pitch 2.5mm"
  rect 1.17x1.91 smd: 1(-3.75,4.065) 2(-1.25,4.065) 3(1.25,4.065) 4(3.75,4.065) 5(3.75,-4.065) 6(1.25,-4.065) 7(-1.25,-4.065) 8(-3.75,-4.065)
  silkscreen extent -5.25,-3.8 4.89,3.8, body extent -4.89,-4.57 4.89,4.57, height 10.56

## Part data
C900: "CAP, CERM, 2200 pF, 300 V, +/- 20%, E, TH, 2- Leads, Body 9x7mm, Pin Spacing 7.5mm"
C901: library part EEUED2W330S, "CAP ALUM 100UF 400V 20% RADIAL"
C902: "CAP, CERM, 22 µF, 16 V, +/- 20%, X5R, 1206"
C903: library part ECQ-U3A104MG, "CAP FILM 0.33UF 10% 275V RADIAL"
C904 C905 C906: library part UVY2G4R7MPD, "CAP ALUM 680UF 6.3V 20% RADIAL"
C907: library part 6SEPC220M, "CAP ALUM 470UF 6.3V 20% RADIAL"
C908: "CAP, CERM, 1 µF, 16 V, +/- 10%, X5R, 0603"
C909: "CAP, CERM, 0.1uF, 25V, +/-10%, X7R, 0805"
C910: "CAP, CERM, 100pF, 100V, +/-5%, C0G/NP0, 0603"
C911: "CAP, CERM, 2.2 µF, 25 V, +/- 10%, X5R, 1206"
C912: "CAP, CERM, 0.1uF, 50V, +/-10%, X7R, 0603"
C913 C915 C919 C920 C923 C925: "CAP, CERM, 1uF, 10V, +/-10%, X5R, 0402"
C914 C917 C924 C926: "CAP, CERM, 47uF, 10V, +/-10%, X5R, 1206"
C916 C918 C921 C922: "CAP, CERM, 0.1uF, 6.3V, +/-10%, X5R, 0402"
D900 D904: "Diode, Ultrafast, 600 V, 3 A, SMC"
D901: "Diode, Switching-Bridge, 800V, 4A, TH"
D902: "Diode, Schottky, 30 V, 0.2 A, SOT-23"
D903: "Diode, Ultrafast, 100 V, 0.25 A, SOD-323"
D905: "Diode, Zener, 5.1 V, 500 mW, SOD-123"
D906: "Diode, Ultrafast, 200V, 1A, SMA"
D907 D908: "Diode, Schottky, 30V, 0.2A, SOD-323"
D909: "Diode, Zener, 16 V, 200 mW, SOD-323"
F900: "FUSE BOARD MOUNT 2A 250VAC RAD"
J900 J901 J902 J903: "Connector, Shielded USB Type A, Gold, R/A, TH"
J904: "AC Receptacle, 2.5A, R/A, TH"
J905: "Jumper Wire, 300mil spacing, Orange, pkg of 200"
L900: "Coupled inductor, 4 mH, 1.5 A, 0.14 ohm, +/- 30%, TH"
Q900 Q903: library part IPP50R199CP, "MOSFET N CH 500V 9.9A PGTO220"
Q901: "MOSFET, N-CH, 60 V, 0.17 A, SOT-23"
Q902: "MOSFET, N-CH, 40 V, 100 A, SON 5x6mm"
R900: "RES, 3.0, 5%, 0.1 W, 0603"
R901: "RES, 100 k, 5%, 0.1 W, 0603"
R902: "RES, 1.0 k, 5%, 0.1 W, 0603"
R903: "RES, 0 ohm, 5%, 0.125W, 0805"
R904: "RES, 324 k, 1%, 0.1 W, 0603"
R905: "RES, 182 k, 1%, 0.1 W, 0603"
R906: "RES, 0, 5%, 0.1 W, 0603"
R907: "RES, 10.0 k, 1%, 0.1 W, 0603"
R908: "RES, 30.1 k, 1%, 0.1 W, 0603"
R909: "RES, 10.0, 1%, 0.125 W, 0805"
R910: "RES, 25.5 k, 1%, 0.1 W, 0603"
R911: "RES, 133 k, 1%, 0.1 W, 0603"
R912: "RES, 100k ohm, 5%, 0.125W, 0805"
R913: "RES, 976, 1%, 0.1 W, 0603"
R914: library part CSRN2010FKR300, "RES SMD 0.33 OHM 1% 1/2W 2010"
R915: "RES, 0.4, 1%, 1 W, 2010"
R916 R917: "RES, 56.2 k, 1%, 0.1 W, 0603"
R918: "RES, 36.5 k, 1%, 0.1 W, 0603"
R919 R920 R923 R924: "RES, 10.0k ohm, 1%, 0.063W, 0402"
R921 R922 R925 R926: "RES, 44.2 k, 1%, 0.063 W, 0402"
T900: "Transformer, 750 uH, TH"
T900: "Transformer, 90 uH, TH"
U900: "SYNCRONOUS RECTIFIER CONTROLLER WITH LOW POWER STANDBY, DBV0006A"
U901: "Constant-Voltage Constant-Current Flyback Controller With PSR and Wake-Up Monitoring, D0007A"
U902 U903 U910 U911: "Precision Adjustable Current-Limited Power-Distribution Switch, DRC0010A"
U904 U905 U908 U909: "Low-Capacitance + / - 15 kV ESD-Protection Array for High-Speed Data Interfaces, 2 Channels, -40 to +85 degC, 5-pin SOT (DRL), Green (RoHS & no Sb/Br)"
U906 U907: "DUAL CHANNEL AUTO DETECT USB CHARGING CONTROLLER, DBV0006A"

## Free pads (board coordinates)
  rect 0x0 / inner rect 0x0 / far side round 0 hole 0.762 slot 7.62 at 90 deg: 0(21.336,17.78)

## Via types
v1: diameter 0.711, hole 0.254, Top Layer to Bottom Layer, 44 vias
v2: diameter 0.5, hole 0.2, Top Layer to Bottom Layer, 16 vias
v3: diameter 1.524, hole 0.762, Top Layer to Bottom Layer, 1 vias

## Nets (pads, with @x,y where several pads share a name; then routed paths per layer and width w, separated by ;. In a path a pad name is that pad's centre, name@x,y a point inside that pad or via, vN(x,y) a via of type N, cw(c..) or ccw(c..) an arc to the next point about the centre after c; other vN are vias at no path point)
GND: C900.2 C901.2 C911.2 C912.2 D901.4 D904.2 Q901.2 R914.1 R915.1 R916.1 R917.1 R918.1 T900.6@37.084,14.732 U901.4 | length 117.4
  Top Layer w0.635: v1(35.085,6.604) 35.085,8.277 35.878,9.07 C911.2@38.608,9.07 39.296,8.382 39.828,8.382 v1(40.64,7.57) C900.2@45.322,7.57
  Top Layer w2.54: D901.4@3.81,36.576 3.81,45.78 C901.2@5.08,47.05
  Bottom Layer w0.635: R915.1@23.1,21.59 24.818,21.59 32.512,13.896 32.512,9.906 U901.4@35.052,7.366 ; Q901.2@29.398,12.884 30.473,13.959 ; U901.4@35.179,7.239 U901.4@35.179,6.49 34.859,6.169 34.859,3.388 35.744,2.502 R916.1@35.851,2.502 R917.1@37.375,2.502 ; 35.306,7.62 36.394,8.708 37.266,8.708 ; T900.6@37.084,14.732 37.266,14.55 37.266,12.7 37.284,12.682 37.284,10.944 37.266,10.927 37.266,8.708 ; v1(40.64,7.57) 39.806,7.57 39.806,7.629 39.328,8.107 37.867,8.107 37.266,8.708
  Bottom Layer w1.905: D904.2@23.1,42.67 R914.1@23.1,25.146 R915.1@23.1,21.59 31.333,13.371 31.496,13.208
  Bottom Layer w2.54: C901.2@5.08,47.05 21.772,47.05 D904.2@23.876,44.958
  other v1: 25.4,25.4 25.4,26.595 21.336,42.672 24.13,42.672 22.682,43.434
  other v3: 27.432,17.78
GND2: C900.1 C902.2 C904.2 C905.2 C906.2 C907.2 C908.2 C909.2 C913.2 C914.2 C915.2 C916.2 C917.2 C918.2 C919.2 C920.2 C921.2 C922.2 C923.2 C924.2 C925.2 C926.2 J900.4 J900.5 J900.6 J900.7 J901.4 J901.5 J901.6 J901.7 J902.4 J902.5 J902.6 J902.7 J903.4 J903.5 J903.6 J903.7 Q902.1 Q902.2 Q902.3 R901.1 R902.1 R903.2 R907.1 R908.1 R910.2 R921.1 R922.1 R925.1 R926.1 U900.5 U902.1 U902.11 U903.1 U903.11 U904.4 U905.4 U906.2 U907.2 U908.4 U909.4 U910.1 U910.11 U911.1 U911.11 | length 294.1
  Top Layer w0.305: v1(66.028,30.988) 67.038,29.978 67.038,28.658 66.574,28.194 v1(66.136,28.194)
  Top Layer w0.635: v1(57.531,25.128) 58.311,25.908 64.262,25.908 64.262,26.775 65.069,27.581 65.069,27.783 65.372,28.086 66.029,28.086 v1(66.136,28.194)
  Top Layer w1.27: C900.1@53.28,7.112 53.28,43.668 C905.2@54.102,44.49
  Bottom Layer w0.254: C915.2@72.906,26.658 73.422,26.142 U903.1@73.422,25.784 73.468,25.738 73.468,24.388 v2(73.472,24.384)
  Bottom Layer w0.305: C923.2@64.77,41.664 65.118,42.012 65.888,42.012 66.693,42.817 U910.11@67.056,43.18 ; C922.2@66.04,4.834 66.04,4.71 66.768,3.982 67.462,3.982 U909.4@68.064,4.584 69.092,3.556 69.968,3.556 J903.4@70.29,3.234 ; C921.2@66.04,39.378 C921.2@66.144,39.378 ; 66.04,50.252 C916.2@66.04,51.824 C916.2@66.144,51.824 ; U910.11@67.572,43.696 R925.1@67.572,45.466 ; U908.4@68.064,39.128 68.906,38.286 J902.4@70.29,38.286 ; U904.4@68.064,51.574 68.906,50.732 J900.4@70.29,50.732 ; U911.11@73.422,11.226 73.422,11.684 U911.11@73.422,11.954 ; U911.11@74.938,10.66 R926.1@76.708,10.66
  Bottom Layer w0.508: 67.268,58.166 68.03,58.928 68.814,58.928 J900.6@72.21,55.532 75.21,55.532 J900.7@77.91,52.832 ; U910.11@67.31,43.434 67.31,45.328 66.662,45.976 66.649,45.976 66.336,46.289 66.336,47.315 66.602,47.581 66.94,47.581 v1(66.94,47.752) 69.088,47.752 69.81,48.474 69.81,50.252 ; U902.11@67.318,55.888 R921.1@67.318,57.912 ; J902.6@72.21,43.086 J900.5@72.21,50.132
  Bottom Layer w0.635: C905.2@54.102,44.49 57.531,41.061 C902.2@57.531,29.718 ; R903.2@54.12,25.128 v1(56.261,25.128) 56.642,25.128 ; v1(57.531,25.128) v1(58.801,25.128) ; C918.2@66.04,17.026 66.04,16.51 66.548,16.002 67.29,16.002 67.296,16.008 67.428,16.008 68.064,16.644 U905.4@68.064,16.776 69.16,15.68 J901.4@70.29,15.68 73.672,15.68 C917.2@74.422,16.43 C917.2@74.93,16.43 ; U907.2@67.748,11.684 U911.11@73.422,11.684 ; J903.4@70.29,3.234 70.89,2.634 J903.5@72.21,2.634 73.072,2.634 C926.2@74.422,3.984 ; J901.6@71.882,20.808 71.882,24.13 72.136,24.384 v2(73.472,24.384) ; J903.6@72.21,8.034 72.21,9.726 U911.11@73.66,11.176 ; J901.5@72.21,15.08 72.21,14.057 72.856,13.411 72.856,13.052 73.152,12.756 73.152,11.954
  Bottom Layer w1: C906.2@61.976,51.856 63.286,51.856 ; v1(66.028,30.988) 66.536,30.48 R910.2@66.536,29.464 ; R907.1@66.536,26.394 R908.1@66.536,27.94 ; U910.11@66.693,42.817 66.693,41.955 66.598,41.86 65.736,41.86 65.278,41.402 65.024,41.402 65.024,39.644 65.69,38.978 65.69,38.196 66.08,37.806 67.493,37.806 67.883,38.196 70.2,38.196 70.71,37.686 J902.5@72.21,37.686 73.214,37.686 C924.2@74.39,38.862 ; U902.11@67.056,55.626 66.731,55.301 66.731,54.439 66.583,54.291 65.721,54.291 63.286,51.856 ; C907.2@75.926,32.766 75.926,34.056 75.476,34.506 R902.1@75.476,34.544 R901.1@75.476,36.176 75.476,37.982 C924.2@74.422,39.036 76.56,39.036 J902.7@77.91,40.386 ; J900.7@77.91,52.832 77.91,51.494 77.148,50.732 J900.4@70.29,50.732 69.81,50.252 66.04,50.252 65.318,50.252 63.714,51.856 63.286,51.856
  Bottom Layer w1.27: C926.2@74.422,3.984 76.56,3.984 J903.7@77.91,5.334 J901.7@77.91,17.78 ; U903.11@74.56,24.522 76.56,24.522 77.327,25.289 ; C917.2@74.93,16.43 76.091,16.43 77.793,18.132 77.793,23.768 77.327,24.234 77.327,25.289 ; C909.2@75.692,30.734 77.327,29.099 77.327,25.289 ; C909.2@75.926,30.968 C907.2@75.926,32.766
  Bottom Layer w2.54: C904.2@46.228,51.856 56.642,41.442 56.642,25.908 ; C905.2@54.61,44.49 C906.2@61.976,51.856
  other v1: 67.31,11.684
  other v2: 74.422,10.601 73.472,11.176 75.372,11.176 74.422,11.751 74.422,23.809 75.372,24.384 74.422,24.959 67.056,42.23 66.481,43.18 67.631,43.18 67.056,44.13 67.056,54.676 66.481,55.626 67.631,55.626 67.056,56.576
NetC901_1: C901.1 J905.2 Q900.2 | length 41.1
  Bottom Layer w1.905: C901.1@5.08,54.55 20.525,54.55 27.483,47.592 27.483,41.519 26.91,40.946 J905.2@26.91,40.386 26.91,37.967 29.063,35.814 Q900.2@32.004,35.814
NetC903_1: C903.1 F900.1 L900.4 | length 17.6
  Top Layer w2.54: F900.1@2.286,21.082 3.91,21.082 C903.1@6.45,18.542 ; 3.382,21.61 L900.4@3.382,25.182
  Bottom Layer w2.54: F900.1@2.286,21.082 3.91,21.082 3.382,21.61 L900.4@3.382,25.182 ; 4.398,20.594 C903.1@6.45,18.542
NetC903_2: C903.2 J904.2 L900.1 | length 35.1
  Top Layer w2.54: L900.1@13.382,25.182 13.382,24.11 C903.2@18.95,18.542 13.572,13.164 J904.2@13.572,12.19
  Bottom Layer w2.54: L900.1@13.382,25.182 13.382,24.11 C903.2@18.95,18.542 13.572,13.164 J904.2@13.572,12.19
NetC910_1: C910.1 R903.1 | length 2.3
  Bottom Layer w0.635: C910.1@52.032,22.86 R903.1@52.032,25.184
NetC910_2: C910.2 Q902.5 Q902.6 Q902.7 Q902.8 R904.2 T900.7@62.484,14.732 T900.8@62.484,18.542 T900.9 | length 12.6
  Bottom Layer w0.635: C910.2@53.632,22.86 56.388,22.86 ; T900.9@62.484,22.352 66.04,22.352 66.536,22.848 R904.2@66.536,24.638
  Bottom Layer w1.905: 58.674,22.352 T900.9@62.484,22.352
  other v1: 56.896,21.082 58.42,21.082 59.944,21.082 56.896,22.606 58.42,22.606 59.944,22.606
NetC911_1: C911.1 C912.1 D905.2 R909.1 U901.1 | length 13.5
  Top Layer w0.635: v1(30.226,6.096) 31.242,5.08 37.338,5.08 38.403,6.145 v1(39.008,6.145)
  Bottom Layer w0.635: U901.1@38.989,6.49 39.383,6.096 R909.1@42.672,6.096
NetC914_1: C914.1 C916.1 J900.1 U902.7 U902.8 U902.9 U904.1 | length 11.9
  Bottom Layer w0.254: C916.1@66.04,52.824 66.29,53.074 U904.1@67.064,53.074 67.056,53.082 67.056,53.594 67.31,53.848 69.088,53.848 70.172,54.932 J900.1@70.29,54.932 ; U902.9@68.456,55.126 U902.8@68.456,55.626 U902.7@68.456,56.126
  Bottom Layer w0.75: J900.1@70.29,54.932 70.54,54.682 70.842,54.682 71.367,54.157 71.628,54.157
  Bottom Layer w1: 69.596,55.626 J900.1@70.29,54.932 ; 71.628,54.157 74.422,54.157 C914.1@74.422,54.182
NetC917_1: C917.1 C918.1 J901.1 U903.7 U903.8 U903.9 U905.1 | length 13.2
  Top Layer w0.75: J901.1@70.29,19.88 70.54,19.63 70.842,19.63 71.266,19.206 71.266,19.158 71.294,19.13 v1(73.914,19.13)
  Bottom Layer w0.254: C918.1@66.04,18.026 66.29,18.276 U905.1@67.064,18.276 67.064,18.804 68.14,19.88 J901.1@70.29,19.88
  Bottom Layer w0.635: J901.1@70.29,19.88 70.544,19.88 71.294,19.13 v1(73.914,19.13)
NetC921_1: C921.1 C924.1 J902.1 U908.1 U910.7 U910.8 U910.9 | length 13.1
  Bottom Layer w0.254: C921.1@66.04,40.378 66.29,40.628 U908.1@67.064,40.628 67.064,41.156 67.31,41.402 69.206,41.402 J902.1@70.29,42.486 ; U910.9@68.456,42.68 U910.8@68.456,43.18 ; U910.7@68.456,43.68 U910.8@68.456,43.18 ; 68.834,43.18 U910.8@68.456,43.18
  Bottom Layer w0.75: J902.1@70.29,42.486 70.54,42.236 70.842,42.236 71.242,41.836 74.422,41.836 C924.1@74.422,41.736
  Bottom Layer w1: 68.834,43.18 69.596,43.18 J902.1@70.29,42.486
